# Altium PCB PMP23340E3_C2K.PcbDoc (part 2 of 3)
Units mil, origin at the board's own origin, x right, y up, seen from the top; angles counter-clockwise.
Board outline 2299.21 x 1157.48 mil, 14 copper layers (Top Layer, Layer 1, Layer 2, Layer 3, Layer 4, Layer 5, Layer 6, Layer 7, Layer 8, Layer 9, Layer 10, Layer 11, Layer 12, Bottom Layer), stack 130 mil thick; 241 components, 70 nets, 1009 pads, 327 vias.
Unrouted connection lines stored in the file: 7.
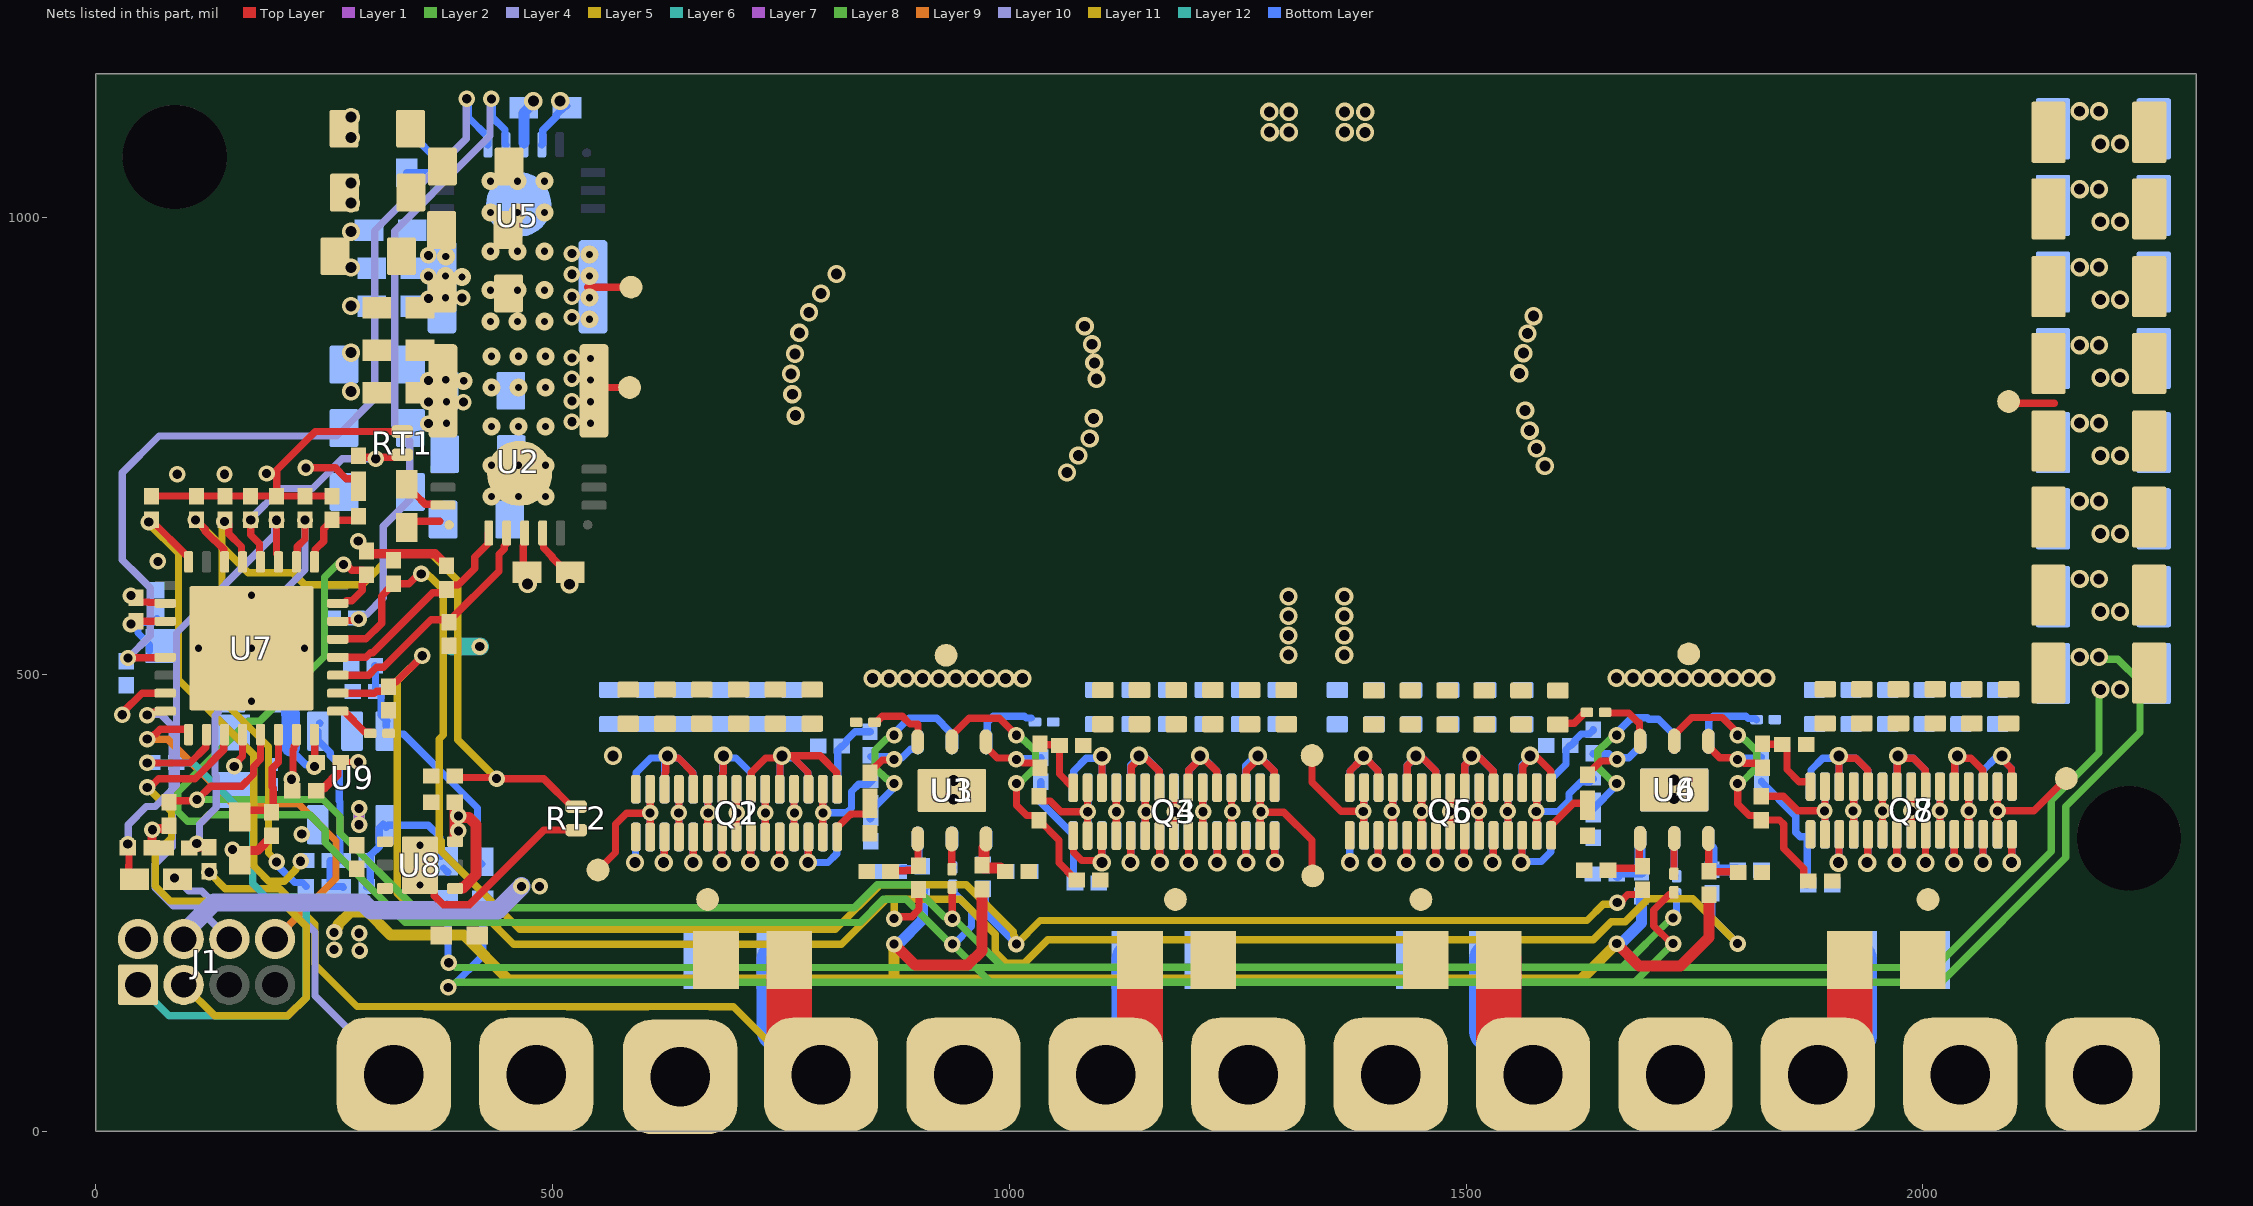
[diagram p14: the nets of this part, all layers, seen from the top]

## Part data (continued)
U7: library part CMP-0097759-1, "Real-Time Microcontrollers VQFN32 TMS320C28x 32bit 120MHz", Frequency_Fixed=120MHz, Manufacturer="Texas Instruments", Max Supply Voltage=3.63V, Min Supply Voltage=1.14V, Operating Temperature Range="-40°C to +125°C"
U8: library part CMP-0013427-7, "500mA LDO, DRV0006A (WSON-6)", Alternate Manufacturer="Texas Instruments"
U9: library part CMP-0032028-2, "CMOS Amplifier 1 Circuit Rail-to-Rail SOT-23-5", Digikey Part Number=296-TLV365DBVRCT-ND, Input Bias Current=0.000005uA, Input Offset Voltage=0.4mV, Manufacturer="Texas Instruments", Max Supply Voltage=5.5V, Min Supply Voltage=2.2V, Mouser Part Number=595-TLV365DBVR, Nominal Supply Current=4.6mA, Operating Temperature Range="-40°C to +125°C", Output Current Per Channel=85mA, Voltage Gain=120dB
ZZ1: library part CMP-0003616-3
ZZ2: library part CMP-0077236-1
ZZ3: library part CMP-0077237-1
ZZ4: library part CMP-0077238-1

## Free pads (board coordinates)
  round 114.17 hole 114.17 unplated: 2(86.41,1066.47) 2(2225.59,320.81)

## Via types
v1: diameter 20, hole 12, Top Layer to Bottom Layer, tented both sides, 153 vias
v2: diameter 18, hole 10, Top Layer to Bottom Layer, tented both sides, 121 vias
v3: diameter 19.68, hole 7.87, Top Layer to Bottom Layer, tented both sides, 51 vias
v4: diameter 19.68, hole 7.87, Top Layer to Bottom Layer, 2 vias

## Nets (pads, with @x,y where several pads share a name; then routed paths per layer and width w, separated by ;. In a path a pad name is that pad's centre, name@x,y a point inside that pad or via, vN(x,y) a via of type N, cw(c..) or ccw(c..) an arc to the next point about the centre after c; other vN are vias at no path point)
3_3V_A: C101.1 C133.1 R9.2 U7.11 | length 87.5
  Top Layer w8: C133.1@45.97,555.72 45.97,555.79 48.35,558.16 U7.11@75.96,558.15
  Bottom Layer w8: C101.1@58.86,525.62 58.86,532.64 46.14,545.35 46.14,552.38 50.83,557.06 63.17,557.06 R9.2@67.04,560.93
  other v2: 38.39,555.12
3_3V_D: C84.1 C106.1 C134.1 C135.1 R9.1 R10.2 R12.2 R31.2 R32.2 U7.15 U7.20 U7.23 U8.1 U9.5 | length 450.2
  Top Layer w8: v2@29.03,456.51 29.03,457.89 50.56,479.41 U7.15@75.96,479.41 ; v2@149.9,398.52 149.9,399.62 160.61,410.32 U7.20@160.61,434.14 ; v2(214.32,385.25) 215.98,386.91 215.98,417.59 216.9,418.51 216.9,421.64 218.74,423.48 218.74,433.21 U7.23@219.67,434.14 ; v2(230.03,726.08) 262.11,726.08 273.92,714.27 283.44,714.27 R31.2@288.04,709.67 ; R12.2@287.54,695.14 287.54,709.17 R31.2@287.71,709.34
  Top Layer w12: v2@288.7,354.31 v2@290.43,352.58
  Layer 1 w12: v2@287.23,333.89 288.33,334.99 v2(288.33,335.48) v2(288.33,353.31)
  Layer 2 w12: v2@288.33,334.82 v2(288.33,335.48) v2(288.33,353.31)
  Layer 4 w12: v2@288.12,335.32 v2(288.33,335.48) v2(288.33,353.31)
  Layer 5 w12: v2(288.33,353.31) 288.33,335.64 v2@288.47,335.5
  Layer 6 w12: v2(288.33,353.31) 288.33,337.95 v2@289.72,336.56
  Layer 7 w12: v2@288.12,336.56 288.33,336.77 v2(288.33,353.31)
  Layer 8 w12: v2@287.58,336.38 288.33,337.13 v2(288.33,353.31)
  Layer 9 w12: v2@287.41,336.03 288.33,336.95 v2(288.33,353.31)
  Layer 10 w12: v2@287.94,334.61 288.33,334.99 v2(288.33,335.48) v2(288.33,353.31)
  Layer 11 w12: v2@288.33,335.71 v2(288.33,353.31)
  Layer 12 w12: v2@287.05,334.61 v2@288.33,335.88 ; v2@287.23,334.43 v2(288.33,335.48) v2@288.33,335.88 ; v2(288.33,353.31) v2@288.33,335.88
  Bottom Layer w12: v2(288.33,353.31) v2(288.33,335.48) 288.33,335.19 v2@289.13,334.38
  other v2: 225.51,325.26 151.57,399.24 29.03,455.83 67.95,623.71
5V: C12.2 C48.2 C83.1 J1.2 L1.1 L2.1 L3.1 L4.1 U2.14 U5.14 U8.4 U8.6 | length 2270.2
  Top Layer w8: C12.2@467.81,616.28 467.81,641.21 468.61,642.01 U2.14@468.61,657.45 ; C12.2@471.58,615.54 472.77,614.34 v1(472.77,599.09)
  Top Layer w12: C83.1@392.99,360.1 393.21,359.88 393.21,344.89 v2@393.44,344.66 ; v2@393.06,325.22 393.06,316.99 393.16,316.9 U8.6@393.21,316.9 ; U8.6@393.28,316.9 U8.6@393.21,316.9 ; U8.4@396.14,265.81 398.65,265.81 399.22,266.39 401.78,266.39 416.14,280.74 416.14,335.7 408.33,343.52 394.58,343.52 v2@393.44,344.66 ; v2(873.92,204.75) 896.77,181.9 899.17,181.9 ; 899.17,181.75 954.97,181.75 ; 954.97,182.3 970.05,197.38 L2.1@970.05,265.17 ; v2(1664.88,205.38) 1689.35,180.91 1734.6,180.91 1765.81,212.12 L4.1@1765.81,258.78 1765.81,259.15 L4.1@1764.48,260.49 ; U8.6@393.21,316.9 393.12,316.99 393.12,328.11 392.95,328.28 393.19,328.52 393.19,344.42 v2@393.44,344.66
  Layer 1 w12: J1.2@46.09,206.08 J1.2@46.09,211.13
  Layer 11 w12: v2(260.93,217.57) 260.93,219.2 265.18,223.44 265.18,226.21 278.65,239.68 297.71,239.68 322.8,214.59 402.95,214.59 451.79,165.75 1619.05,165.75 ; 872.73,166.53 873.92,167.72 v2(873.92,204.75) ; 1619.05,165.67 1625.18,165.67 v2(1664.88,205.38)
  Bottom Layer w12: U5.14@468.5,1081.69 468.5,1114.8 479.51,1125.8 C48.2@479.51,1126.45 ; v2(873.92,204.75) 875.07,205.89 879.57,205.89 904.71,231.03 L1.1@904.71,263.99 904.71,265 L1.1@905.56,265.85 ; v2(1664.88,205.38) 1666.03,206.52 1670.53,206.52 1691.8,227.79 1691.8,257.17 L3.1@1690.96,258
  other v1: 479,1127.46
  other v2: 260.93,198.84 396.86,328.77 396.86,345.15
AGND: C83.2 C84.2 C85.2 C86.2 C87.2 C88.1 C89.1 C90.2 C91.2 C92.2 C93.2 C94.2 C95.2 C96.1 C100.2 C101.2 C103.1 C104.1 C106.2 C107.1 C108.1 C109.1 C133.2 C134.2 C135.2 C136.2 NT1.2 R11.1 R13.2 R23.1 R24.1 R26.1 RT1.2 RT2.2 U7.10 U7.33 U8.3 U8.7@354.9,291.31 U9.2 | length 969.4
  Top Layer w8: C133.2@44.85,584.75 44.85,582.73 48.35,579.23 57.32,579.23 57.79,578.76 75.04,578.76 U7.10@75.96,577.84 ; C88.1@61.15,695.09 61.27,695.21 C136.2@258.69,695.21 ; C104.1@197.97,695.22 197.97,723.72 240.18,765.92 RT1.2@335.5,765.92 335.64,765.92 RT1.2@335.99,766.27 ; C100.2@269.34,403.59 v2@287.41,403.59 ; U8.7@353.56,270.38 364.02,270.38 370.58,263.81 370.58,257.82 380.6,247.81 408.66,247.81 490.45,329.59 RT2.2@525.89,329.59
  Top Layer w10: R24.1@61.11,310.32 61.53,310.73 61.53,329.9 v2@61.21,330.21 ; R24.1@61.54,311 62.45,310.09 76.52,310.09 R23.1@76.57,310.04 ; v2@61.87,329.55 63.77,331.45 77.4,331.45 C90.2@80.1,334.15 ; v2(149.65,308.28) 157.78,300.15 R13.2@157.78,296.55 157.78,300.48 164.6,307.3 177.32,307.3 193.29,323.26 C85.2@193.38,323.26 ; U7.33@160.61,465.71 166.9,472 U7.33@171.22,472 ; C135.2@241.29,372.67 244.55,375.94 250.03,375.94 252.36,378.27 263.98,389.89 263.98,400.28 266.29,402.58 C100.2@266.29,403.16 ; v2@287.97,647.1 287.97,644.23 C91.2@296.29,635.91 ; C91.2@295.2,632.36 295.48,632.07 371.35,632.07 381.83,621.6 C92.2@381.83,619.47
  Layer 12 w20: 389.83,530.52 v2(420.27,530.52)
  other v2: 288.77,197.66 288.18,216.68 61.94,329.92 287.41,404.14 38.47,586.33 287.26,646.01 89.19,719.13 140.91,719.13 186.97,719.94
  other v3: 170.45,470.55 112.38,528.62 170.45,528.62 228.52,528.62 170.45,586.7
  other v4: 354.9,269.65 354.9,312.96
DCT2A: C91.1 R1.1 R44.1 U7.31 | length 2363.5
  Top Layer w8: U7.31@262.66,578.7 272.69,578.7 274.59,580.6 280.57,580.6 291.82,591.85 291.82,599.5 C91.1@296.08,603.77 ; v2@270.93,623.26 280.16,614.04 292.05,614.04 296.32,609.77 C91.1@296.32,609.11 ; v2@1726.73,205.42 1724.82,205.42 1705.55,224.7 1705.55,242.1 1722.12,258.67 1726.28,258.67 1727.45,259.84 R44.1@1727.45,261.64
  Layer 2 w8: v2@939.38,203.05 979.1,163.33 1684.5,163.33 v2(1726.55,205.38)
  Layer 8 w8: v2@267.87,624.02 250.37,606.51 250.37,519.58 179.5,448.71 166.79,448.71 89.81,371.72 89.81,349.89 100.3,339.4 116.88,339.4 123.74,346.26 234.2,346.26 251.33,329.14 251.33,315.93 338.79,228.47 836.7,228.47 862.01,253.77 886.98,253.77 936,204.75 v2(937.68,204.75)
  Bottom Layer w8: v2(937.68,204.75) 939.35,204.75 958.68,224.07 958.68,241.47 939.16,260.98 939.16,268.18 R1.1@938.52,268.82 ; v2@1723.45,205.67 v2@1728.51,205.67
  other v2: 271.14,620.34
DCT2B: C90.1 R38.1 R39.1 U7.21 | length 1957.5
  Top Layer w8: C90.1@78.47,360.06 79.99,361.58 109.36,361.58 v2(110.81,363.03) 111.08,363.03 125.79,377.74 159.77,377.74 172.57,390.54 172.57,399.06 180.3,406.78 180.3,433.58 U7.21@179.52,434.36 ; R38.1@937.66,267.45 937.47,267.25 937.47,232.98 v2(937.68,232.77)
  Layer 2 w8: v2(937.68,232.77) 939.35,232.77 992.8,179.33 1670.8,179.33 v2@1724.24,232.77
  Layer 8 w8: v2(110.81,363.03) 248.82,363.03 267.33,344.52 267.33,326.33 349.19,244.47 441.84,244.47 ; 442.98,244.47 830.08,244.47 855.38,269.77 893.61,269.77 928.69,234.68 935.76,234.68 v2(937.68,232.77)
  Bottom Layer w8: v2@1726.92,234.05 1726.92,236.48 1730.4,239.96 R39.1@1730.4,259.07
  other v2: 1726.55,233.4
GND: C1.1 C2.1 C3.1 C4.1 C5.1 C6.1 C7.1 C8.1 C9.1 C10.1 C11.2 C12.1 C14.1 C15.1 C16.1 C17.1 C18.1 C19.1 C20.1 C21.1 C22.1 C23.1 C24.1 C25.1 C26.1 C27.1 C28.1 C29.1 C30.1 C31.1 C32.1 C33.1 C34.1 C35.1 C36.1 C37.1 C38.2 C42.2 C48.1 C51.1 C52.1 C53.1 C54.1 C55.1 C56.1 C57.1 C58.1 C59.1 C60.1 C61.1 C62.1 C66.1 C67.1 C68.1 C69.1 C70.1 C71.1 C72.1 C73.1 C74.1 C75.1 C76.1 C77.1 C80.2 C97.1 C98.2 C99.1 C110.2 C111.1 C112.2 C113.1 C114.2 C115.2 C116.2 C117.2 C118.2 C119.2 C120.2 C121.2 C122.2 C123.2 C124.2 C125.2 C126.2 C127.2 C128.2 C129.1 C130.1 C131.1 C132.1 C137.1 C138.1 Gnd1.1 Gnd2.1 Gnd3.1 Gnd4.1 Gnd5.1 Gnd6.1 J1.4 NT1.1 Q1.2 Q1.5 Q1.6 Q1.9 Q1.10 Q1.13 Q1.14 Q1.17 Q1.18 Q1.21 Q1.22 Q1.25 Q1.26 Q1.29 Q1.30 Q2.2 Q2.5 Q2.6 Q2.9 Q2.10 Q2.13 Q2.14 Q2.17 Q2.18 Q2.21 Q2.22 Q2.25 Q2.26 Q2.29 Q2.30 Q3.2 Q3.5 Q3.6 Q3.9 Q3.10 Q3.13 Q3.14 Q3.17 Q3.18 Q3.21 Q3.22 Q3.25 Q3.26 Q3.29 Q3.30 Q4.2 Q4.5 Q4.6 Q4.9 Q4.10 Q4.13 Q4.14 Q4.17 Q4.18 Q4.21 Q4.22 Q4.25 Q4.26 Q4.29 Q4.30 Q5.2 Q5.5 Q5.6 Q5.9 Q5.10 Q5.13 Q5.14 Q5.17 Q5.18 Q5.21 Q5.22 Q5.25 Q5.26 Q5.29 Q5.30 Q6.2 Q6.5 Q6.6 Q6.9 Q6.10 Q6.13 Q6.14 Q6.17 Q6.18 Q6.21 Q6.22 Q6.25 Q6.26 Q6.29 Q6.30 Q7.2 Q7.5 Q7.6 Q7.9 Q7.10 Q7.13 Q7.14 Q7.17 Q7.18 Q7.21 Q7.22 Q7.25 Q7.26 Q7.29 Q7.30 Q8.2 Q8.5 Q8.6 Q8.9 Q8.10 Q8.13 Q8.14 Q8.17 Q8.18 Q8.21 Q8.22 Q8.25 Q8.26 Q8.29 Q8.30 R4.1 R8.1 R19.1 R22.1 R30.1 R34.1 R36.1 R45.1 TP12.1 TP13.1 TP14.1 TP15.1 U1.7@937.3,373.03 U2.6 U2.15 U3.7@937.01,373.03 U4.7@1727.87,373.66 U5.6 U5.15 U6.7@1727.87,373.66 | length 4876.3
  Top Layer w8: U2.15@489.22,654.82 490.14,653.9 490.14,638.49 499.79,628.84 499.79,627.62 C12.1@516.87,610.53 ; v1(518.55,598.71) 519.15,599.31 C12.1@519.15,612 ; v1(621.65,294.17) 622.2,294.73 622.2,321.65 Q1.25@622.83,322.28 ; Q1.26@623.07,369.66 623.07,392.64 623.76,393.34 623.76,408.53 v1(626.06,410.83) ; v1@626.02,411.34 628.84,408.53 637.81,408.53 652.72,393.62 ; 652.44,393.35 653.7,392.1 653.7,374.86 Q1.22@654.13,374.43 ; v1(653.96,294.17) 654.05,294.26 654.05,322.75 Q1.21@654.49,323.2 ; Q1.17@685.24,312.49 685.48,312.26 685.48,294.72 685.93,294.27 685.83,294.17 v1(685.33,294.17) ; Q1.18@685.93,379.23 686.06,379.36 686.06,391.66 686.89,392.49 v1(686.89,410.83) ; v1(716.53,294.17) 716.83,294.47 716.83,322.47 Q1.13@717.55,323.2 ; Q1.14@717.12,374.43 717.55,374.86 717.55,392.64 733.44,408.53 749.05,408.53 749.05,374.86 Q1.10@748.62,374.43 ; Q1.9@748.34,308.39 v1@748.34,294.21 ; v1@750.16,412.48 751.81,410.83 792.99,410.83 811.18,392.64 811.18,374.86 Q1.2@811.61,374.43 ; 763.79,408.53 779.68,392.64 779.68,374.86 Q1.6@780.11,374.43 ; v1(779.5,294.17) 779.81,294.48 779.81,316.24 Q1.5@779.68,316.36 ; Q3.2@1069.89,323.46 1070.32,323.03 1070.32,305.25 1079.25,296.32 1100.24,296.32 v1@1101.32,295.25 ; v1@1098.88,411.11 1101.38,408.61 Q3.5@1101.39,375.82 ; Q3.6@1101.39,323.46 1101.32,323.39 v1@1101.32,295.25 ; v1@1101.61,294.95 v1@1101.32,295.25 ; Q3.10@1132.88,323.46 1132.75,323.32 1132.75,295.71 v1@1134.64,293.81 ; Q3.9@1132.88,375.82 1133.32,376.26 1133.32,398.85 1141.7,407.23 v1@1141.7,410.83 ; v1@1142.38,411.11 1144.97,408.53 1149.45,408.53 1163.95,394.04 1163.95,376.26 Q3.13@1164.38,375.82 ; v1@1164.25,294.5 1164.65,294.9 1164.65,323.19 Q3.14@1164.38,323.46 ; v1@1194.54,291.31 1196.08,292.85 1196.08,323.25 Q3.18@1195.87,323.46 ; Q3.17@1195.87,375.82 1196.31,376.26 1196.31,395.1 v1@1209.58,408.37 ; v1@1209.12,410.2 1210.77,410.2 1226.94,394.04 1226.94,376.26 Q3.21@1227.37,375.82 ; v1@1226.2,292.22 1227.43,293.45 1227.43,323.4 Q3.22@1227.37,323.46 ; v1@1258.55,293.58 1259.1,294.14 1259.1,323.22 Q3.26@1258.87,323.46 ; Q3.25@1258.87,375.82 1259.3,376.26 1259.3,394.9 1273.35,408.95 v1@1273.35,410.43 ; v1@1272.44,411.11 1272.85,411.11 1289.93,394.04 1289.93,376.26 Q3.29@1290.36,375.82 ; Q3.30@1290.36,323.46 1290.53,323.29 1290.53,293.94 v1@1291.57,292.9 ; Q5.30@1372.56,376.14 1372.99,376.58 1372.99,394.36 1384.73,406.1 v1@1384.73,412.25 ; v1@1386.1,409.98 1388.35,409.98 1403.62,394.7 1403.62,376.58 Q5.26@1404.05,376.14 ; v1@1402.04,294.72 1403.62,296.3 1403.62,323.35 Q5.25@1404.05,323.78 ; v1@1434.61,295.18 1435.12,295.68 1435.12,323.35 Q5.21@1435.55,323.78 ; Q5.22@1435.55,376.14 1435.55,400.21 v1@1445.32,409.98 ; v1@1445.32,408.57 1452.41,408.57 1466.61,394.36 1466.61,376.58 Q5.18@1467.05,376.14 ; v1@1466.96,294.72 1466.61,295.07 1466.61,323.35 Q5.17@1467.05,323.78 ; v1@1497.02,293.58 1498.11,294.67 1498.11,323.35 Q5.13@1498.54,323.78 ; Q5.14@1498.54,376.14 1498.54,400.63 1503.36,405.45 1503.36,411.38 v1@1503.17,411.57 ; v1@1504.08,411.8 1507.32,408.57 1515.4,408.57 1529.61,394.36 1529.61,376.58 Q5.10@1530.04,376.14 ; Q5.9@1530.04,323.78 1529.61,323.35 1529.61,293.57 v1@1530.28,292.9 ; v1@1560.57,291.99 1561.1,292.52 1561.1,323.35 Q5.5@1561.54,323.78 ; Q5.6@1561.54,376.14 1561.97,376.58 1561.97,399.62 1568.77,406.43 v1@1568.77,409.52 ; v1@1570.36,409.52 1571.32,408.57 1578.39,408.57 1592.6,394.36 1592.6,376.58 Q5.2@1593.03,376.14 ; C31.1@1600.51,444.67 1602.33,446.49 1618.31,446.49 1629.21,457.39 1631.01,457.39 R45.1@1632.18,458.56 ; v1@1908.15,292.9 1908.11,292.94 1908.11,324.49 Q7.6@1908.51,324.89 ; v1@1908.27,406.67 1908.27,377.49 Q7.5@1908.51,377.25 ; v1@1909.06,410.66 1911.41,408.31 1926.73,408.31 1939.57,395.47 1939.57,377.68 Q7.9@1940.01,377.25 ; v1@1938.44,292.45 1939.57,293.57 1939.57,324.46 Q7.10@1940.01,324.89 ; v1@1971.45,294.75 1971.45,324.83 Q7.14@1971.5,324.89 ; Q7.13@1971.5,377.25 1971.93,377.68 v1@1971.93,410.61 ; v1@1972.15,411.11 1974.96,408.31 1989.72,408.31 2002.57,395.47 2002.57,377.68 Q7.17@2003,377.25 ; Q7.18@2003,324.89 2002.88,324.77 2002.88,294.52 v1@2003.13,294.27 ; v1@2034.11,293.81 2034.23,293.93 2034.23,324.62 Q7.22@2034.49,324.89 ; Q7.21@2034.49,377.25 2034.93,377.68 2034.93,404.61 2037.3,406.98 v1@2037.3,409.75 ; v1@2034.79,412.25 v1@2037.3,409.75 ; v1@2037.3,412.03 v1@2037.3,409.75 ; Q7.26@2065.99,324.89 2065.9,324.79 2065.9,293.91 v1@2066.22,293.58 ; Q7.25@2065.99,377.25 2065.56,377.68 2065.56,395.47 2052.71,408.31 2038.73,408.31 v1@2037.3,409.75 ; v1@2088.32,409.29 2088.32,405.74 2097.05,397.01 2097.05,377.68 Q7.29@2097.49,377.25 ; Q7.30@2097.49,324.89 2097.33,324.73 2097.33,295.96 v1@2098.34,294.95 ; v1@748.34,294.21 v1(748.37,294.17)
  Layer 4 w20: J1.4@96.2,210.27 96.2,216.79 106.15,226.74 106.15,226.86 129.61,250.32 292.72,250.32 301.23,241.81 439.78,241.81 v2@465.99,268.02
  Bottom Layer w8: U5.15@488.19,1079.72 489.11,1080.65 489.11,1095.58 504,1110.46 504,1112.27 513.84,1122.1 C48.1@515.64,1122.1 ; v1@587.54,294.27 590.71,297.44 590.71,321.64 Q2.30@591.14,322.06 ; Q2.29@591.14,374.43 591.57,374.86 591.57,392.64 607.46,408.53 v1@622.84,408.53 ; v1(621.65,294.17) 622.2,294.73 622.2,322.84 Q2.26@622.54,323.18 ; Q2.25@622.63,374.43 622.63,404.15 623.76,405.28 623.76,409.05 v1@622.84,409.98 ; v1@623.75,411.8 627.02,408.53 637.81,408.53 653.7,392.64 653.7,374.86 Q2.21@654.13,374.43 ; v1@654.05,297 654.05,321.98 Q2.22@654.13,322.06 ; v1@683.66,294.27 685.48,296.09 685.48,321.92 Q2.18@685.63,322.06 ; v1@683.88,412.71 688.06,408.53 700.8,408.53 716.69,392.64 716.69,374.86 Q2.13@717.12,374.43 ; Q2.17@685.63,374.43 686.06,374.86 v1@686.06,409.87 ; Q2.18@685.72,321.97 Q2.18@685.76,322.01 ; v1(716.53,294.17) 714.93,294.17 714.86,294.25 716.83,296.22 716.83,318.86 Q2.14@716.69,319 ; v1@748.11,294.27 748.5,294.65 748.5,321.94 Q2.10@748.62,322.06 ; Q2.9@748.62,374.43 749.05,374.86 v1@749.05,410.83 ; v1@751.53,410.89 753.89,408.53 763.79,408.53 779.68,392.64 779.68,374.86 Q2.5@780.11,374.43 ; v1@779.81,292.93 779.81,321.76 Q2.6@780.11,322.06 ; v1@780.78,294.17 801.5,294.17 811.18,303.85 811.18,321.63 Q2.2@811.61,322.06 ; Q4.2@1069.98,376.14 1070.42,376.57 1070.42,394.35 1084.2,408.14 1099.09,408.14 v1@1100.02,409.06 ; v1@1100.93,296.32 1101.36,296.75 1101.36,323.66 Q4.5@1101.48,323.78 ; v1@1101.43,408.88 1101.43,376.19 Q4.6@1101.48,376.14 ; v1@1130.77,296.09 1132.79,298.11 1132.79,323.59 Q4.9@1132.98,323.78 ; Q4.10@1132.98,376.14 1132.98,400.6 1139.88,407.5 v1@1139.88,411.8 ; v1@1142.59,411.37 1145.43,408.53 1149.86,408.53 1164.04,394.35 1164.04,376.57 Q4.14@1164.47,376.14 ; Q4.13@1164.47,323.78 1164.7,323.55 1164.7,295.41 v1@1165.85,294.27 ; v1@1195.23,294.95 1196.13,295.85 1196.13,323.62 Q4.17@1195.97,323.78 ; Q4.18@1195.97,376.14 1196.4,376.57 1196.4,395.19 1206.62,405.41 v1@1206.62,410.43 ; v1@1212.09,409.29 1227.03,394.35 1227.03,376.57 Q4.22@1227.46,376.14 ; Q4.21@1227.46,323.78 1227.48,295.72 v1@1228.48,294.72 ; Q4.25@1258.96,323.78 1259.15,323.59 1259.15,293.21 v1@1259.23,293.13 ; Q4.26@1258.96,376.14 1258.96,399.91 v1@1269.94,410.89 ; v1@1273.81,410.57 1290.02,394.35 1290.02,376.57 Q4.30@1290.46,376.14 ; Q4.29@1290.46,323.78 1290.58,323.65 1290.58,295.04 v1@1290.66,294.95 ; v1@1372.43,295.18 1372.8,295.54 1372.8,323.55 Q6.30@1372.56,323.78 ; Q6.29@1372.56,376.14 1372.99,376.58 1372.99,394.36 v1@1385.65,407.01 ; v1@1388.38,409.52 1388.81,409.52 1403.62,394.7 1403.62,376.58 Q6.25@1404.05,376.14 ; v1@1401.36,293.59 1403.62,295.85 1403.62,323.35 Q6.26@1404.05,323.78 ; Q6.22@1435.55,323.78 1435.12,323.35 1435.12,296.73 v1@1436.21,295.63 ; Q6.21@1435.55,376.14 1435.55,400.43 v1@1444.64,409.52 ; v1@1447.83,412.25 1447.83,411.24 1450.5,408.57 1452.41,408.57 1466.61,394.36 1466.61,376.58 Q6.17@1467.05,376.14 ; v1@1466.28,294.5 1466.61,294.83 1466.61,323.35 Q6.18@1467.05,323.78 ; v1@1496.11,292.45 1498.11,294.44 1498.11,323.35 Q6.14@1498.54,323.78 ; Q6.13@1498.54,376.14 1498.54,400.63 v1@1504.09,406.18 ; v1@1507.05,411.11 1509.6,408.57 1515.4,408.57 1529.61,394.36 1529.61,376.58 Q6.9@1530.04,376.14 ; v1@1527.32,294.04 1529.61,296.33 1529.61,323.35 Q6.10@1530.04,323.78 ; v1@1559.89,294.04 v1@1561.1,295.25 ; Q6.6@1561.54,323.78 1561.1,323.35 1561.1,295.3 1582.33,295.3 1592.6,305.57 1592.6,323.35 Q6.2@1593.03,323.78 ; Q6.5@1561.54,376.14 1561.54,400.63 1567.41,406.5 v1@1567.41,412.25 ; Q8.2@1877.01,377.25 1877.45,377.68 1877.45,395.47 1890.29,408.31 1905.58,408.31 v1@1907.01,409.75 ; v1@1907.92,291.53 1908.11,291.72 1908.11,324.49 Q8.5@1908.51,324.89 ; v1@1908.27,408.94 1908.27,377.49 Q8.6@1908.51,377.25 ; v1@1908.9,408.31 1926.73,408.31 1939.57,395.47 1939.57,377.68 Q8.10@1940.01,377.25 ; v1@1938.9,292.9 1939.57,293.57 1939.57,324.46 Q8.9@1940.01,324.89 ; v1@1969.42,294.5 1971.45,296.52 1971.45,324.83 Q8.13@1971.5,324.89 ; v1@1971.47,410.66 1971.93,410.2 1971.93,377.68 Q8.14@1971.5,377.25 ; v1@1974.2,410.66 1976.55,408.31 1989.72,408.31 2002.57,395.47 2002.57,377.68 Q8.18@2003,377.25 ; v1@2002.22,293.81 2002.88,294.47 2002.88,324.77 Q8.17@2003,324.89 ; Q8.21@2034.49,324.89 2034.23,324.62 2034.23,294.6 v1@2034.79,294.04 ; Q8.22@2034.49,377.25 2034.93,377.68 2034.93,404.61 2036.84,406.53 v1@2036.84,410.89 ; Q8.25@2065.99,324.89 2065.9,324.79 2065.9,296.87 v1@2067.13,295.63 ; Q8.26@2065.99,377.25 2066.42,377.68 2066.42,395.47 2079.27,408.31 2082.1,408.31 v1@2084.67,410.89 ; v1@2087.18,406.88 2097.05,397.01 2097.05,377.68 Q8.30@2097.49,377.25 ; v1@2096.06,295.18 2097.33,296.44 2097.33,324.73 Q8.29@2097.49,324.89
  other v1: 590.28,294.17 1101.25,294.17 1132.61,294.17 1164.93,294.17 1196.29,294.17 1227.5,294.17 1259.34,294.17 1290.7,294.17 1373.03,294.29 1402.24,294.21 1434.55,294.21 1465.92,294.21 1497.12,294.21 1528.96,294.21 1560.33,294.21 1907.71,293.96 1939.07,293.96 1971.39,293.96 2002.75,293.96 2033.96,293.96 2065.8,293.96 2097.17,293.96 938.68,363.34 1727.55,363.97 938.68,384.03 1727.55,384.66 566.06,410.83 751.06,410.83 1101.38,410.43 1142.05,410.83 1208.79,410.83 1271.98,410.83 1387.46,410.86 1444.96,410.86 1505.79,410.86 1569.96,410.86 1908.03,410.61 1973,410.61 2037.68,410.61 2086.7,410.61 279.32,809.88 279.32,852.18 279.32,903.25 279.32,945.55 279.32,984.65 279.32,1015.9 279.32,1038.12 279.32,1087.73 279.32,1109.95 508.28,1127.73
  other v2: 465.84,268.03 485.86,268.03
  other v3: 433.11,694.66 462.64,694.66 492.17,694.66 433.11,728.91 462.64,728.91 492.17,728.91 433.11,771.43 462.64,771.43 492.17,771.43 433.11,813.95 462.64,813.95 492.17,813.95 433.11,848.21 462.64,848.21 492.17,848.21 432.09,886.34 461.61,886.34 491.14,886.34 432.09,920.59 461.61,920.59 491.14,920.59 432.09,963.11 461.61,963.11 491.14,963.11 432.09,1005.63 461.61,1005.63 491.14,1005.63 432.09,1039.88 461.61,1039.88 491.14,1039.88
IOCP: C88.2 R18.2 U7.8 | length 556.6
  Top Layer w8: v2(58,666.77) 62.63,666.77 98.47,630.92 100.63,630.92 101.67,629.89 U7.8@101.67,624.28
  Layer 5 w8: v2@58,665.03 90.54,632.49 90.54,494.23 172.75,412.01 172.75,290.73 176.98,286.5 176.98,286.06 189.28,273.76 206.68,273.76 218.98,286.06 218.98,287.46 224.26,292.73 v2(224.26,295.44)
IOSNS: C89.2 R27.2 U7.5 | length 500.5
  Top Layer w8: v2(140.8,667.38) 142.45,667.38 145.65,664.18 145.65,653.88 159.54,639.99 U7.5@159.54,622.59
  Layer 5 w8: v2@138.1,671.67 138.1,472.01 188.97,421.15 188.97,304.44 197.98,295.43 v2(197.98,294.76)
  Bottom Layer w8: v2(197.98,294.76) 199.9,292.84 199.9,290.1 217.86,272.14 226.2,272.14 R27.2@230.47,267.87
JTAG_TCK: J1.6 U7.16 | length 347.2
  Top Layer w8: v2(56.36,455.51) 59.07,455.51 62.36,458.81 75.84,458.81 U7.16@76.89,459.85 ; J1.6@141.72,210.49 J1.6@146.42,210.49
  Layer 10 w8: v2@58.17,456.41 70.95,456.41 83.8,443.56 83.8,311.32 65.23,292.75 65.23,266.19 84.48,246.94 109.53,246.94 J1.6@146.2,210.27
JTAG_TDI: J1.3 U7.19 | length 661.7
  Top Layer w8: v2(56.36,376.35) 59.07,376.35 68.64,385.93 108.53,385.93 140,417.41 140,433.21 U7.19@140.93,434.14
  Layer 5 w8: v2(56.36,376.35) 82.94,349.77 82.94,321.22 65.23,303.51 65.23,268.32 81.57,251.98 202.64,251.98 230.25,224.37 230.25,146.17 210.3,126.22 130.25,126.22 96.95,159.52 J1.3@96.18,159.52
JTAG_TDO: J1.8 U7.17 | length 440.1
  Top Layer w8: v2(56.36,429.22) 59.07,429.22 64.36,434.51 65.06,434.51 70.64,440.09 100.63,440.09 102.08,438.65 U7.17@102.08,438 ; J1.8@195.81,211.35 J1.8@197.28,211.35
  Layer 9 w8: v2(56.36,429.22) 78.77,429.19 149.71,358.26 222.21,358.26 262.91,317.56 262.91,276.98 J1.8@196.59,210.66
JTAG_TMS: J1.1 R10.1 U7.18 | length 677.7
  Top Layer w8: v2(56.36,403.11) 103.08,403.11 120.32,420.35 120.32,439 U7.18@121.88,440.56
  Layer 6 w8: J1.1@45.7,160.92 45.7,160.77 J1.1@46.2,160.27 80.25,126.22 210.3,126.22 230.25,146.17 230.25,246.4 220.21,256.44 186.37,256.44 171.71,271.1 171.71,338.36 106.96,403.11 v2(56.36,403.11)
NetC11_1: C11.1 L1.2 U1.3 | length 55.6
  Bottom Layer w8: C11.1@879.13,284.45 881.9,287.21 L1.2@903.15,287.21 ; U1.3@899.89,319.88 901,318.78 901,294.91 L1.2@904.54,291.37
NetC13_1: C13.1 U2.10 | length 45
  Top Layer w8: C13.1@343.65,703.22 343.65,701.01 348.29,696.37 350.5,696.37 360.61,686.25 379.04,686.25 U2.10@379.96,685.33
NetC13_2: C13.2 U2.11 | length 40.1
  Top Layer w8: C13.2@340.29,659.18 340.29,659.51 348.58,667.8 376.67,667.8
NetC38_1: C38.1 L2.2 U3.3 | length 60.4
  Top Layer w12: U3.3@974.59,320.1 974.59,312.69 972.32,310.42 972.32,293.28 L2.2@970.05,291.01 970.05,290.35 972.32,288.08 990.56,288.08 995,283.64 C38.1@995,282.56
NetC42_1: C42.1 L3.2 U4.3 | length 65.9
  Bottom Layer w12: C42.1@1665.81,279.95 1665.81,281.4 1667.87,283.46 L3.2@1691.8,283.46 1690.47,284.79 U4.3@1690.47,320.51
NetC50_1: C50.1 U5.10 | length 45.1
  Bottom Layer w8: C50.1@340.55,1049.21 U5.10@378.94,1049.21 384.36,1049.21 U5.10@385.29,1050.14
NetC50_2: C50.2 U5.11 | length 61
  Bottom Layer w8: C50.2@340.55,1096.46 340.55,1092.52 348.36,1084.71 352.3,1084.71 368.01,1069 U5.11@387.86,1069
NetC80_1: C80.1 L4.2 U6.3 | length 68.2
  Top Layer w8: U6.3@1763.7,318.15 1765.54,316.3 L4.2@1765.54,285.19 ; L4.2@1764.07,285.19 1765.23,284.02 1797.06,284.02 C80.1@1797.8,283.29
NetC96_2: C96.2 C100.1 U7.24 | length 127.3
  Top Layer w8: U7.24@238.73,436.46 239.55,435.64 C100.1@239.55,404.11
  Bottom Layer w8: 213.3,420.02 213.3,417.44 229.73,401.01 237.32,401.01 v2(239.23,399.09)
  Bottom Layer w20: C96.2@207.07,475.91 212.82,470.16 212.82,456.96 213.3,456.48 213.3,420.02
NetC97_2: C97.2 Q1.1 R3.1 | length 65.4
  Top Layer w8: Q1.1@811.61,322.06 811.61,332.38 826.11,346.88 827.37,346.88 ; 827.38,347.16 C97.2@843.19,347.16 ; C97.2@846.47,349.2 847.46,350.18 C97.2@847.46,352.09 R3.1@847.46,366.31
NetC98_1: C98.1 Q2.1 R5.2 | length 78
  Bottom Layer w8: Q2.1@812.07,384.21 812.07,385.12 812.31,385.36 812.31,417.24 816.58,421.51 C98.1@816.71,421.51 ; C98.1@816.92,420.93 821.77,425.78 821.77,427.92 831.13,437.29 R5.2@847.6,437.29
NetC99_2: C99.2 Q3.1 R7.1 | length 70.4
  Top Layer w8: R7.1@1033.45,424 1034.33,423.12 C99.2@1052.31,423.12 ; C99.2@1054.92,422.24 1054.92,390.94 Q3.1@1068.95,376.91
NetC105_1: C105.1 R16.1 R18.1 R27.1 U9.1 | length 208.5
  Bottom Layer w8: U9.1@243.11,437.99 243.11,428.15 256.7,414.56 256.7,411.33 266.41,401.62 266.41,361.59 267.33,360.67 267.33,298.81 C105.1@269.23,296.91 ; U9.1@245.29,446.41 U9.1@245.36,446.48 ; R27.1@255.99,267.88 256.07,267.8 269.92,267.8 R16.1@270.86,266.85 ; R27.1@256.31,268.2 R18.1@256.31,296.37 C105.1@269.23,296.37 ; R16.1@270.39,267.8 R16.1@270.47,267.72
NetC105_2: C105.2 R16.2 R17.2 U9.4 | length 168.4
  Bottom Layer w8: R16.2@296.46,267.72 300.31,271.57 C105.2@300.31,302.32 ; C105.2@301.12,302.34 310.31,311.53 310.31,331.52 U9.4@314.69,335.9 ; U9.4@317.91,332.68 320.04,334.8 363.94,334.8 376.74,322.01 376.74,319.19 377.53,318.4 R17.2@377.53,300.9 ; R17.2@380.53,288.17 R17.2@385.16,283.54
NetC107_2: C107.2 R25.2 R26.2 U9.3 | length 268.8
  Bottom Layer w8: R26.2@305.4,509.5 306.27,508.63 306.27,483.13 C107.2@307.8,481.59 ; C107.2@307.13,481.45 307.92,481.45 312.18,477.18 312.18,455.35 U9.3@318.73,448.8 ; U9.3@318.1,437.15 320.57,434.68 337.04,434.68 417.86,353.85 417.86,297.31 R25.2@422.72,292.45 ; U9.3@318.12,443.31 U9.3@318.12,447.6
NetC110_1: C110.1 Q4.1 R37.2 | length 124.3
  Bottom Layer w8: R37.2@1034.45,382.68 1034.45,359.95 Q4.1@1068.84,325.55 ; Q4.1@1069.98,323.78 1070.19,323.57 1070.19,274.88 C110.1@1072.96,272.11
NetC111_2: C111.2 Q5.1 R40.1 | length 77.4
  Top Layer w8: Q5.1@1593.03,323.78 1593.37,324.12 Q5.1@1593.37,336.63 ; Q5.1@1594.37,335.64 1617.65,358.92 1628.61,358.92 1632.5,362.82 R40.1@1632.5,363.98 ; C111.2@1631.98,350.1 C111.2@1632.18,350.3 ; C111.2@1632.87,349.61 R40.1@1632.87,363.19
NetC112_1: C112.1 Q6.1 R41.2 | length 76.4
  Bottom Layer w8: Q6.1@1593.49,385.92 1609.34,401.77 1609.34,417.77 1613.61,422.04 C112.1@1613.87,422.04 ; C112.1@1615.57,422.96 1618.92,426.31 1618.92,427.65 1625.96,434.68 1634.93,434.68 1639.2,438.95 R41.2@1639.2,439.61
NetC113_2: C113.2 Q7.1 R42.1 | length 87.3
  Top Layer w8: R42.1@1824.36,424 1824.75,423.62 C113.2@1845.78,423.62 ; C113.2@1846.26,423.23 1846.92,423.23 1851.19,418.96 1851.19,395.87 1864.39,382.68 1875.7,382.68 1877.01,381.36 Q7.1@1877.01,377.25
NetC114_1: C114.1 Q8.1 R43.2 | length 138.5
  Bottom Layer w8: R43.2@1823.34,383.31 1823.34,382.52 1860.95,344.91 1860.95,327.07 1865.64,322.38 1872.14,322.38 Q8.1@1872.54,321.98 ; C114.1@1872.94,269.22 1873.48,269.75 Q8.1@1873.48,321.98
NetC129_2: C129.2 R14.2 U1.1 | length 56.1
  Bottom Layer w8: R14.2@971.46,291.54 973.59,293.67 973.59,320.62 U1.1@976.1,323.12 ; R14.2@975.72,287.99 993.31,287.99 C129.2@996.85,284.45
NetC130_2: C130.2 R15.2 U3.1 | length 61.4
  Top Layer w8: C130.2@871.2,285.07 886.81,285.07 887.35,285.62 896.32,285.62 900.1,289.4 900.1,319.39 U3.1@899.61,319.88
NetC131_2: C131.2 R28.2 U4.1 | length 65.8
  Bottom Layer w12: U4.1@1765.27,320.51 1765.27,313.14 1769.16,309.26 R28.2@1769.16,286.33 ; R28.2@1769,286.21 1769.29,285.92 1796.32,285.92 C131.2@1798.12,284.12
NetC132_2: C132.2 R29.2 U6.1 | length 71.9
  Top Layer w8: C132.2@1655.32,285.6 1657.58,287.86 R29.2@1691.93,287.86 ; U6.1@1689.63,322.96 1689.63,293.7 R29.2@1693.21,290.11
NetR1_2: R1.2 U1.2 | length 32.4
  Bottom Layer w6: U1.2@937.3,319.88 937.64,319.53 937.64,289.43 R1.2@938.93,288.14
NetR2_1: R2.1 R4.2 U1.5 | length 211.1
  Layer 2 w8: v2@873.92,434.33 871.22,434.33 866.14,429.26 865.22,429.26 852.92,416.96 852.92,397.99 865.18,385.74 866.26,385.74 870.69,381.31 v2@874.63,381.31
  Bottom Layer w8: R4.2@847.69,341.64 848.29,342.24 R4.2@848.29,343.35 R2.1@848.29,358.7 ; R2.1@852.45,354.55 872.01,374.11 872.01,379.08 v2@873.92,380.99 ; v2@874.81,436.69 890.08,451.96 920.39,451.96 934.41,437.95 934.41,437.52 937.3,434.63 U1.5@937.3,428.17
  other v2: 873.92,380.79 873.92,433.35
NetR6_1: R6.1 R8.2 U3.5 | length 294.3
  Top Layer w8: U3.5@938.04,432.58 938.04,434.17 955.83,451.96 989.14,451.96 v2(1007.75,433.35) ; v2@1005.89,378.21 1007.75,376.35 1007.75,356.91 1019.18,345.49 1028.15,345.49 1032.41,341.22 R6.1@1032.41,340.56 1054.35,318.63 1054.35,293.69 1070.6,277.43 R8.2@1072.05,277.43
  Layer 2 w8: v2(1007.75,433.35) 1010.46,433.35 1015.78,428.03 1016.45,428.03 1028.75,415.73 1028.75,398.34 1013.12,382.7 1012.37,382.7 1009.52,379.84 v2@1009.52,378.81
  other v2: 1007.75,380.79
NetR11_2: R11.2 U7.25 | length 45.7
  Top Layer w8: U7.25@264.94,459.73 271.83,459.73 294.55,437.01 R11.2@301.2,437.01
NetR19_2: R19.2 U3.6 | length 73.1
  Top Layer w8: R19.2@852.42,447.69 854.21,447.69 860.87,454.35 882.62,454.35 891.18,445.79 899.97,445.79 U3.6@899.97,426.62
NetR22_2: R22.2 U1.6 | length 74.1
  Bottom Layer w8: U1.6@974.7,426.18 975.8,427.29 975.8,447.63 982.52,454.35 1016.45,454.35 1018.48,452.32 R22.2@1024.35,452.32
NetR30_2: R30.2 U4.6 | length 78.2
  Bottom Layer w8: U4.6@1765.27,426.81 1765.6,427.14 1765.6,451.4 ; 1767.32,451.4 1770.27,454.35 1805.97,454.35 1808.63,451.69 1816.78,451.69 R30.2@1817.95,450.52
NetR33_1: R33.1 R34.2 U4.5 | length 199.1
  Layer 2 w8: v2(1664.88,433.35) 1662.17,433.35 1656.86,428.03 1656.57,428.03 1644.27,415.73 1644.27,398.34 1659.91,382.7 1664.36,382.7 v2@1667.42,379.63
  Bottom Layer w8: R33.1@1638.08,353.59 1639.63,353.59 v2@1662.97,376.92 ; v2@1665.39,432.08 1665.39,436.57 1679.77,450.94 1681,450.94 1682.65,452.59 1698.29,452.59 1699.94,450.94 1710.63,450.94 1727.87,433.7 U4.5@1727.87,426.81
  other v2: 1664.88,380.79
NetR35_1: R35.1 R36.2 U6.5 | length 322.1
  Top Layer w8: U6.5@1727.03,432.86 1746.96,452.79 1780.54,452.79 1797.52,435.81 v2@1797.52,433.1 ; v2(1797.27,380.79) 1797.27,358.09 1809.87,345.49 1819.23,345.49 R35.1@1823.28,341.44 ; R35.1@1823.11,339.77 R35.1@1823.11,340.56 1843.11,340.56 1847.8,335.87 1847.8,309.38 1869.61,287.57 1869.61,278.12 R36.2@1874.93,272.8
  Layer 2 w8: v2@1794.97,380.82 1796.84,382.7 1802.64,382.7 1818.27,398.34 1818.27,415.73 1805.97,428.03 1805.29,428.03 1799.98,433.35 v2(1797.27,433.35)
NetR38_2: R38.2 U3.2 | length 32.7
  Top Layer w8: R38.2@937.26,286.84 937.14,286.97 937.14,318 U3.2@938.22,319.08
NetR39_2: R39.2 U4.2 | length 41.8
  Bottom Layer w8: U4.2@1727.87,320.51 1727.87,280.48 R39.2@1729.15,279.21
NetR44_2: R44.2 U6.2 | length 44.3
  Top Layer w8: R44.2@1727.45,281.66 1727.66,281.87 1727.66,324.7 U6.2@1728.51,325.56
NetR45_2: R45.2 U6.6 | length 60.3
  Top Layer w8: R45.2@1653.29,457.74 1678.07,457.74 1688.39,447.42 ; 1689.74,447.42 1689.74,427.54 U6.6@1690.47,426.81
PWM1A: C92.1 U2.12 U7.28 | length 237.6
  Top Layer w8: U7.28@264.94,518.78 295.7,518.78 300.63,523.71 303.15,523.71 368.9,589.46 379.44,589.46 385.65,595.67 385.65,597.87 396.94,597.87 414.92,615.85 414.92,628.63 429.24,642.95 429.24,654.52 U2.12@430.33,655.61
PWM1B: C93.1 U2.13 U7.27 | length 272.9
  Top Layer w8: U7.27@264.94,499.1 298.64,499.1 307.25,507.71 314.94,507.71 366.96,559.72 384.06,559.72 C93.1@386.52,557.26 ; C93.1@386.52,558.05 441.41,612.93 441.41,631.55 447.08,637.22 447.08,640.35 448.93,642.2 448.93,656.07 U2.13@449.89,657.03
PWM2A: C95.1 R14.1 R29.1 U7.29 | length 1963.3
  Top Layer w8: U7.29@264.94,538.47 265.51,539.04 295.85,539.04 312.94,556.13 312.94,585.88 321.22,594.16 321.51,594.16 325.78,598.43 C95.1@325.78,599.21 342.77,599.21 355.72,612.16 v2@357.32,612.16 ; v2(1665.41,250.23) 1668.11,250.23 1676.95,259.07 1688.94,259.07 1694.15,264.28 R29.1@1694.15,265.24
  Layer 11 w8: v2@358.04,614.14 365.44,606.74 366.01,606.74 380.33,592.43 380.33,433.74 375.86,429.27 375.86,322.89 375.86,320.07 378.32,317.61 378.32,306.4 463.97,220.75 809.57,220.75 858.6,269.77 953,269.77 1004.62,218.16 1004.62,214.43 1005.84,213.21 1005.84,209.18 v2@1004.62,207.96 ; v2(1007.75,204.75) 1033.66,230.66 1632.44,230.66 1650.1,248.32 1663.04,248.32 v2@1664.95,250.23
  Bottom Layer w8: R14.1@970.56,265.42 973.49,262.49 973.49,249.29 974.68,248.1 974.68,237.82 v2(1007.75,204.75)
  other v2: 356.27,610.07
PWM2B: C94.1 R15.1 R28.1 U7.26 | length 2129.6
  Top Layer w8: U7.26@264.94,479.41 304.94,479.41 307.25,481.72 316.22,481.72 320.49,485.99 320.49,487.44 324.76,491.71 328.97,491.71 v2@357.32,520.06 ; v2(873.92,232.77) 875.84,234.68 893.07,234.68 901.2,242.81 R15.1@901.2,266.41 ; R15.1@898.64,261.83 R15.1@900.76,259.71
  Layer 11 w8: v2@358.25,521.32 330,493.07 330,260.58 354.32,236.25 425.84,236.25 457.34,204.75 816.2,204.75 865.22,253.77 874.43,253.77 ; v2(873.92,232.77) 873.92,253.27 874.43,253.77 ; v2@1796.92,205.18 1796.92,205.73 1748.25,254.4 1699.27,254.4 1674.1,229.23 1659.04,229.23 1639.21,209.41 1042.11,209.41 1016.45,183.75 996.78,183.75 984.46,196.07 984.46,215.69 946.38,253.77 874.43,253.77
  Bottom Layer w8: R28.1@1769.02,260.67 1769.02,233.62 v2(1797.27,205.38)
  other v2: 357.38,520.45
PWM3A: C87.1 U5.12 U7.13 | length 1001.4
  Top Layer w8: v2@35.26,518.53 35.42,518.37 75.56,518.37 U7.13@75.96,518.78
  Layer 4 w8: v2(35.26,517.97) 59.47,542.17 59.47,595.03 47.17,607.33 46.96,607.33 29,625.3 29,720.9 69.17,761.07 264.05,761.07 305.3,802.32 305.3,985.86 405.63,1086.19 v2@405.63,1128.11
  Bottom Layer w8: v2@405.58,1126.52 407.06,1126.52 408.01,1125.57 408.01,1109.71 429.13,1088.58 U5.12@429.13,1079.72
  other v2: 406.09,1130.19
PWM3B: C86.1 U5.13 U7.30 | length 716.5
  Top Layer w8: U7.30@264.94,558.15 265.86,559.07 286.19,559.07 v2(287.78,560.66)
  Layer 4 w8: v2(287.78,560.66) 290.48,560.66 295.41,565.59 296.54,565.59 314.75,583.8 314.75,662.34 343.55,691.13 343.55,756.16 327.18,772.53 327.18,985.05 411.38,1069.25 ; 411.35,1069.28 431.61,1089.54 v2@431.61,1127.76
  Bottom Layer w8: v2@434,1123.73 434,1110.05 447.9,1096.16 447.9,1080.65 U5.13@448.82,1079.72
  other v2: 433.07,1129.92
RESET: C136.1 R12.1 U7.1 | length 82.4
  Top Layer w8: U7.1@239.35,623.11 240.27,624.03 240.27,636.8 249.38,645.91 249.38,659.48 254.07,664.17 254.42,664.17 258.69,668.43 C136.1@258.69,669.22 ; C136.1@259.44,668.88 287.03,668.88 R12.1@287.36,668.54
SR1A2: R3.2 R5.1 U1.4 | length 96.6
  Top Layer w8: R3.2@849.41,391.02 849.41,395.03 860.73,406.35 872.01,406.35 v2@873.92,408.26
  Bottom Layer w8: R5.1@848.08,410.24 848.54,409.78 872.4,409.78 873.24,408.95 882.38,408.95 883.61,410.18 883.89,410.18 891.9,418.19 897.22,418.19 899.89,420.86 U1.4@899.89,426.18
  other v2: 873.92,407.03
SR1B2: R7.2 R37.1 U3.4 | length 99.3
  Top Layer w8: U3.4@974.41,426.18 974.41,420.86 986.75,408.51 1007.89,408.51 v2@1008.84,407.56 ; v2@1010.46,407.03 1014.55,402.95 1030.73,402.95 R7.2@1034.59,399.09
  Bottom Layer w8: v2@1008.41,407.37 1008.89,407.85 1033.64,407.85 R37.1@1034.45,408.66
  other v2: 1007.75,407.03
SR2A2: R42.2 R43.1 U6.4 | length 99.4
  Top Layer w8: U6.4@1765.27,426.81 1765.27,421.48 1777.81,408.95 v2@1795.9,408.95 ; v2(1797.27,407.03) 1799.98,407.03 1804.09,402.92 1820.1,402.92 R42.2@1824.2,398.83
  Bottom Layer w8: v2@1796.36,407.02 1797.51,408.16 1822.22,408.16 R43.1@1823.34,409.29
SR2B2: R40.2 R41.1 U4.4 | length 104.6
  Top Layer w8: R40.2@1630.01,389.62 R40.2@1631.75,389.62 ; R40.2@1634.48,390.93 1634.48,392.35 1647.25,405.12 1663.36,405.12 v2(1665.27,407.03)
  Bottom Layer w8: R41.1@1639.03,413.18 1656.42,413.18 1662.57,407.03 v2(1665.27,407.03) ; v2@1665.27,408.95 1677.93,408.95 1690.47,421.48 U4.4@1690.47,426.81
TEMP_P: C108.2 R31.1 RT1.1 U7.4 | length 264.6
  Top Layer w8: v2(169.62,668.84) 169.62,652.53 179.17,642.99 U7.4@179.17,622.93 ; R31.1@288.25,737.24 288.84,737.83 332.99,737.83 RT1.1@335.5,740.33 ; RT1.1@335.5,740.73 RT1.1@336.02,741.26
  Layer 4 w8: v2@168.39,669.76 169.05,669.76 202.82,703.53 237.18,703.53 269.77,736.12 v2(306.42,736.12)
TEMP_S: C109.2 R32.1 RT2.1 U7.6 | length 783
  Top Layer w8: v2(109.35,669.13) 109.55,669.13 119.8,658.88 119.8,656.53 129.4,646.92 129.98,646.92 140,636.9 140,623.85 U7.6@140.59,623.26 ; R32.1@392.99,388.64 394.37,387.26 437.38,387.26 v2(438.76,385.88) 490.27,385.88 521.81,354.34 RT2.1@525.99,354.34
  Layer 11 w8: v2@110.07,667.61 110.86,667.61 124.34,654.14 167.05,611.43 215.71,611.43 228.85,598.28 291.95,598.28 326.83,633.16 366.01,633.16 396.33,602.85 396.33,428.32 v2(438.76,385.88)
Vin: C1.2 C2.2 C3.2 C4.2 C5.2 C6.2 C7.2 C8.2 C9.2 C10.2 C123.1 C124.1 C125.1 C126.1 C127.1 C128.1 C137.2 C138.2 R21.2 U2.7 U5.7 Vin1.1 | length 345.6
  Layer 10 w8: v2(86.23,277.01) 87.78,277.01 101.86,262.94 116.16,262.94 127.21,251.89 205.93,251.89 239.93,217.89 239.93,148.17 277.15,110.94 277.15,66.67 Vin1.1@276.63,66.14
  other v2: 364.17,774.61 364.17,798.23 402.45,798.16 364.17,821.85 364.17,911.42 400.94,912.2 364.17,936.02 364.17,958.66
  other v3: 383.9,774.9 383.9,798.52 402.75,821.39 383.14,822.48 382.87,912.4 400.94,935.08 382.87,936.02 383.14,957.6
VINSNS: C104.2 R21.1 R24.2 U7.3 | length 517.4
  Top Layer w8: v2(35.03,314.21) 35.03,313.84 36.57,312.31 36.36,312.1 36.36,291.43 36.15,291.23 R21.1@36.15,269.57 ; v2(197.81,668.82) 197.81,632.17 199.47,630.51 U7.3@199.47,625.29
  Layer 4 w8: v2@35.3,314.51 35.45,314.66 35.45,335.51 55.29,355.35 65.06,355.35 88.39,378.68 88.39,545.37 196.02,653 v2@196.02,670
VOSNS2: C103.2 R20.1 R23.2 U7.2 | length 474.6
  Top Layer w8: R23.2@101.57,310.15 101.81,310.38 123.63,310.38 R20.1@123.97,310.72 ; U7.2@218.76,625.29 220.59,627.12 220.59,639.75 229.02,648.18 v2(229.02,668.84)
  Layer 4 w8: v2@113.49,313.84 113.49,336 131.81,354.33 131.81,389.31 130.57,390.54 130.57,455.09 134.22,458.74 134.22,523.29 163.49,552.56 167.2,552.56 229.02,614.37 229.02,666.45 v2@228.65,666.82
  other v2: 110.48,314.72
Vout: C14.2 C15.2 C16.2 C17.2 C18.2 C19.2 C20.2 C21.2 C22.2 C23.2 C24.2 C25.2 C26.2 C27.2 C28.2 C29.2 C30.2 C31.2 C32.2 C33.2 C34.2 C35.2 C36.2 C37.2 C51.2 C52.2 C53.2 C54.2 C55.2 C56.2 C57.2 C58.2 C59.2 C60.2 C61.2 C62.2 C66.2 C67.2 C68.2 C69.2 C70.2 C71.2 C72.2 C73.2 C74.2 C75.2 C76.2 C77.2 C115.1 C116.1 C117.1 C118.1 C119.1 C120.1 C121.1 C122.1 Q1.3 Q1.4 Q1.7 Q1.8 Q1.11 Q1.12 Q1.15 Q1.16 Q1.19 Q1.20 Q1.23 Q1.24 Q1.27 Q1.28 Q2.3 Q2.4 Q2.7 Q2.8 Q2.11 Q2.12 Q2.15 Q2.16 Q2.19 Q2.20 Q2.23 Q2.24 Q2.27 Q2.28 Q3.3 Q3.4 Q3.7 Q3.8 Q3.11 Q3.12 Q3.15 Q3.16 Q3.19 Q3.20 Q3.23 Q3.24 Q3.27 Q3.28 Q4.3 Q4.4 Q4.7 Q4.8 Q4.11 Q4.12 Q4.15 Q4.16 Q4.19 Q4.20 Q4.23 Q4.24 Q4.27 Q4.28 Q5.3 Q5.4 Q5.7 Q5.8 Q5.11 Q5.12 Q5.15 Q5.16 Q5.19 Q5.20 Q5.23 Q5.24 Q5.27 Q5.28 Q6.3 Q6.4 Q6.7 Q6.8 Q6.11 Q6.12 Q6.15 Q6.16 Q6.19 Q6.20 Q6.23 Q6.24 Q6.27 Q6.28 Q7.3 Q7.4 Q7.7 Q7.8 Q7.11 Q7.12 Q7.15 Q7.16 Q7.19 Q7.20 Q7.23 Q7.24 Q7.27 Q7.28 Q8.3 Q8.4 Q8.7 Q8.8 Q8.11 Q8.12 Q8.15 Q8.16 Q8.19 Q8.20 Q8.23 Q8.24 Q8.27 Q8.28 R2.2 R6.2 R20.2 R33.2 R35.2 TP1.1 TP2.1 TP3.1 TP4.1 TP5.1 TP6.1 Vout1.1 Vout2.1 Vout3.1 Vout4.1 Vout5.1 Vout6.1 | length 5516.1
  Top Layer w8: R20.2@124.38,285.73 R20.2@124.48,285.83 ; TP5.1@548.13,286.93 550.81,286.93 568.84,304.97 568.84,335.85 580.91,347.91 606.29,347.91 v2(606.77,348.4) ; Q1.27@606.89,322.06 Q1.28@606.89,374.43 Q1.28@606.89,376.03 ; Q1.23@638.38,322.06 Q1.24@638.38,374.69 ; Q1.19@669.88,322.06 v2@669.88,350.07 ; Q1.20@669.88,374.43 670.16,374.14 670.16,350.12 v2@670.21,350.07 ; Q1.15@701.37,322.06 Q1.16@701.37,374.43 ; Q1.11@732.87,322.06 Q1.12@732.87,374.43 ; Q1.7@764.37,322.06 Q1.8@764.37,374.43 ; Q1.3@795.66,334.47 v2@795.66,347.84 ; v2@795.86,348.76 Q1.4@795.86,374.43 ; v2(796.23,348.4) v2@796.78,347.84 ; R6.2@1031.11,367.18 1031.11,367.06 1036.68,361.49 1044.81,361.49 1056.65,349.65 v2@1085.64,349.65 ; Q3.4@1085.64,323.46 v2@1085.64,349.65 ; Q3.3@1085.64,375.82 v2@1085.64,349.65 ; v2(1085.84,349.65) v2@1085.64,349.65 ; Q3.8@1117.13,323.46 Q3.7@1117.13,375.82 ; Q3.12@1148.63,323.46 Q3.11@1148.63,375.82 ; Q3.16@1180.13,323.46 Q3.15@1180.13,375.82 ; Q3.20@1211.62,323.46 Q3.19@1211.62,375.82 ; Q3.24@1243.12,323.46 Q3.23@1243.12,375.82 ; Q3.28@1274.61,323.46 Q3.27@1274.61,375.82 ; v2(1275.3,349.65) 1275.71,349.24 1300.53,349.24 1331.4,318.37 TP3.1@1331.4,289.61 ; TP4.1@1331.4,411.23 1331.4,382.06 1363.09,350.36 1387,350.36 v2@1387.26,350.1 ; v2@1386.1,352.58 v2@1387.87,350.8 ; v2(1387.36,350) v2@1387.26,350.1 ; Q5.27@1388.31,323.78 1387.87,324.21 v2@1387.87,350.71 ; Q5.27@1388.31,333.56 Q5.28@1388.31,376.14 1387.87,375.71 v2@1387.87,350.8 ; Q5.23@1419.8,323.78 Q5.24@1419.8,376.14 ; Q5.19@1451.3,323.78 Q5.20@1451.3,376.14 ; Q5.15@1482.8,323.78 Q5.16@1482.8,376.14 ; Q5.11@1514.29,323.78 Q5.12@1514.29,376.14 ; Q5.7@1545.79,333.56 Q5.8@1545.79,376.14 ; Q5.3@1577.28,333.56 Q5.4@1577.28,376.14 ; R35.2@1823.11,366.54 1847.07,366.54 1862.94,350.67 1891.27,350.67 v2@1892.37,351.77 ; Q7.4@1892.76,324.89 v2@1892.76,350.59 ; v2@1892.76,351.77 Q7.3@1892.76,367.47 ; Q7.8@1924.05,336.55 1924.26,336.75 Q7.7@1924.26,377.25 ; Q7.12@1955.75,334.67 Q7.11@1955.75,377.25 ; Q7.16@1987.25,334.67 Q7.15@1987.25,377.25 ; Q7.20@2018.75,334.67 Q7.19@2018.75,377.25 ; Q7.24@2050.24,334.67 Q7.23@2050.24,377.25 ; Q7.28@2081.74,334.67 Q7.27@2081.74,377.25 ; v2(2081.76,350.59) 2081.85,350.67 2121.62,350.67 2154.86,383.9 TP2.1@2154.86,384.97 ; v2@1387.26,350.1 v2@1387.87,350.71 ; v2@1387.87,350.71 v2@1387.87,350.8
  Top Layer w50: C120.1@758.95,187.39 758.95,100.18 793.91,65.22 Vout4.1@793.91,61.81 ; Vout3.1@1105.65,61.81 1105.65,65.22 1143.09,102.66 C119.1@1143.09,187.39 ; C121.1@1535.72,187.39 1535.72,102.77 1573.27,65.22 Vout2.1@1573.27,61.81 ; Vout1.1@1885.02,61.81 1885.02,65.22 1919.87,100.07 C122.1@1919.87,187.39
  Layer 11 w8: v2@125.08,282.19 141.83,265.43 201.41,265.43 207.8,259.04 ; 207.64,258.89 239.93,226.61 239.93,182.39 285.91,136.41 357.59,136.41 cw(c357.59,93.11) 362.42,136.14 446.03,136.14 cw(c450.86,93.11) 450.86,136.41 513.46,136.41 cw(c513.46,93.11) 518.29,136.14 601.9,136.14 cw(c606.74,93.11) 606.74,136.41 669.33,136.41 cw(c669.33,93.11) 674.17,136.14 698.06,136.14 700.4,133.8 774.49,59.71 Vout4.1@788.1,59.71
  Layer 12 w8: Vout4.1@752.16,103.56 Vout4.1@793.91,61.81
  Bottom Layer w8: Q2.28@606.89,322.06 Q2.27@606.89,374.43 ; Q2.24@638.38,322.06 Q2.23@638.38,374.43 ; Q2.20@669.88,322.06 Q2.19@669.88,374.43 ; Q2.16@701.37,322.06 Q2.15@701.37,374.43 ; Q2.12@732.87,322.06 Q2.11@732.87,374.43 ; Q2.8@764.37,322.06 Q2.7@764.37,374.43 ; Q2.4@795.86,322.06 Q2.3@795.86,374.43 ; v2(796.23,348.4) 796.48,348.65 822.11,348.65 827.15,353.69 827.15,371.86 835.05,379.76 845.55,379.76 R2.2@849.31,383.52 ; Q4.3@1085.73,333.56 v2@1085.73,349.65 ; Q4.4@1085.73,376.14 v2@1085.73,349.65 ; v2@1087.62,351.03 1086.25,349.65 v2(1085.84,349.65) v2@1085.73,349.65 ; Q4.7@1117.23,323.78 Q4.8@1117.23,376.14 ; Q4.11@1148.72,323.78 Q4.12@1148.72,376.14 ; Q4.15@1180.22,323.78 Q4.16@1180.22,376.14 ; Q4.19@1211.72,323.78 Q4.20@1211.72,376.14 ; Q4.23@1243.21,323.78 Q4.24@1243.21,376.14 ; Q4.27@1274.71,323.78 Q4.28@1274.71,376.14 ; Q6.28@1388.25,324.14 Q6.27@1388.25,376.5 ; Q6.24@1419.74,324.14 Q6.23@1419.74,376.5 ; Q6.20@1451.24,324.14 Q6.19@1451.24,376.5 ; Q6.16@1482.74,324.14 Q6.15@1482.74,376.5 ; Q6.12@1514.23,324.14 Q6.11@1514.23,376.5 ; Q6.8@1545.79,323.78 Q6.7@1545.79,376.14 ; v2(1576.82,350) v2@1577.28,350 ; Q6.4@1577.28,323.78 v2@1577.28,350 ; Q6.3@1577.28,376.14 v2@1577.28,350 ; R33.2@1639.02,385.94 1635.6,382.52 1625.96,382.52 1612.71,369.27 1612.71,361.9 1600.81,350 v2@1577.28,350 ; Q8.3@1892.76,334.67 Q8.4@1892.76,377.25 ; Q8.7@1924.26,324.89 Q8.8@1924.26,377.25 ; Q8.11@1955.75,324.89 Q8.12@1955.75,377.25 ; Q8.15@1987.25,324.89 Q8.16@1987.25,377.25 ; Q8.19@2018.75,324.89 Q8.20@2018.75,377.25 ; Q8.23@2050.24,324.89 Q8.24@2050.24,377.25 ; Q8.27@2081.74,324.89 Q8.28@2081.74,377.25
  Bottom Layer w50: C118.1@748.49,187.39 748.49,110.64 793.91,65.22 Vout4.1@793.91,61.81 ; Vout3.1@1105.65,61.81 1136.87,93.03 C117.1@1136.87,187.39 ; C116.1@1528.25,187.39 1528.25,110.25 1573.27,65.22 Vout2.1@1573.27,61.81 ; Vout1.1@1885.02,61.81 1885.02,65.22 1924.62,104.82 C115.1@1924.62,187.39
  other v1: 850.37,495.61 868.57,495.61 886.78,495.61 904.99,495.61 923.2,495.61 941.41,495.61 959.61,495.61 977.82,495.61 996.03,495.61 1014.24,495.61 1664.58,496.06 1682.78,496.06 1700.99,496.06 1719.2,496.06 1737.41,496.06 1755.62,496.06 1773.82,496.06 1792.03,496.06 1810.24,496.06 1828.45,496.06
  other v2: 124.22,283.41 638.14,348.4 670.45,348.4 701.82,348.4 733.02,348.4 764.86,348.4 1117.21,349.65 1149.52,349.65 1180.89,349.65 1212.09,349.65 1243.93,349.65 1418.72,350 1451.04,350 1482.4,350 1513.61,350 1545.45,350 1892.31,350.59 1923.67,350.59 1955.99,350.59 1987.35,350.59 2018.56,350.59 2050.4,350.59
Vsw1: C39.2 C40.2 C41.2 C43.2 C44.2 C45.2 C46.2 C47.2 C49.2 C63.2 C64.2 C65.2 C78.2 C79.2 C81.2 C82.2 R25.1 TP7.1 TP9.1 U2.5 | length 2319
  Top Layer w8: U2.5@541.11,812.91 542.35,814.14 TP9.1@584.4,814.14 ; TP7.1@2093.86,798.81 2095.77,796.89 2143.71,796.89
  Layer 8 w8: v2(385.83,157.48) 388.53,157.48 394.26,163.2 2020.15,163.2 2156.5,299.55 2156.5,355.44 2237.66,436.6 2237.66,492.49 2213.47,516.69 2198.42,516.69 2191.46,523.65 v1@2191.46,523.77
  Bottom Layer w8: v2@384.24,158.3 385.33,159.39 391.1,159.39 423.64,191.93 R25.1@423.64,247.81
  other v1: 2171.6,518.99 2192.88,518.99 2171.6,604.34 2192.88,604.34 2171.6,689.69 2192.88,689.69 2171.6,775.05 2192.88,775.05 2171.6,860.4 2192.88,860.4 2171.6,945.76 2192.88,945.76 2171.6,1031.11 2192.88,1031.11 2171.6,1116.46 2192.88,1116.46
  other v2: 521.13,776.51 521.13,799.15 521.13,823.76 521.13,846.4
  other v3: 541.38,774.9 541.38,798.52 541.38,822.14 541.38,845.77
Vsw2: C39.1 C40.1 C41.1 C43.1 C44.1 C45.1 C46.1 C47.1 C49.1 C63.1 C64.1 C65.1 C78.1 C79.1 C81.1 C82.1 R17.1 TP8.1 U5.5 | length 2119.8
  Top Layer w8: 538.61,923.89 TP8.1@585.95,923.89
  Layer 8 w8: v2(386.33,184.33) 389.04,184.33 394.16,179.2 2013.53,179.2 2140.5,306.18 2140.5,362.07 2192.81,414.38 v1@2192.81,484.74
  Bottom Layer w8: R17.1@384.8,248.27 385.57,247.5 385.57,187.38 v2@387.1,185.85
  other v1: 2194.38,483.38 2215.66,483.38 1305.47,521.14 1366.6,521.14 1305.47,542.49 1366.6,542.49 1305.47,563.85 1366.6,563.85 2194.38,568.73 2215.66,568.73 1305.47,585.2 1366.6,585.2 2194.38,654.09 2215.66,654.09 1063.08,721 1586.13,728.07 1075.54,739.65 2194.38,739.44 2215.66,739.44 1577.15,747.42 1087.91,758.12 1569.55,766.76 1092.38,780.3 765.95,783.23 1564.71,788.87 762.45,806.7 1095.44,823.56 2194.38,824.79 2215.66,824.79 760.92,829.09 1558.23,829.64 1093.06,841.04 765.41,850.95 1562.61,851.64 1090.53,861.42 770.19,873.86 1567.1,873.12 1082.51,881.13 1573.81,892.13 780.68,896.33 2194.38,910.15 2215.66,910.15 793.96,917 810.88,938.42 2194.38,995.5 2215.66,995.5 2194.38,1080.86 2215.66,1080.86 1285.03,1093.56 1305.96,1093.56 1367.09,1093.56 1389.21,1093.38 1284.62,1115.8 1305.96,1115.8 1367.09,1115.8 1389.62,1115.62
  other v2: 521.13,890.75 521.13,913.38 521.13,937.99 521.13,960.63
  other v3: 540.35,888.78 540.35,912.4 540.35,936.02 540.35,959.65
X1: C85.1 R13.1 U7.22 | length 123.2
  Top Layer w8: R13.1@157.11,351.29 C85.1@188.98,351.29 ; C85.1@192.42,349.17 194.25,350.99 194.25,375.62 193.32,376.55 193.32,397.18 199.98,403.84 U7.22@199.98,434.14 199.98,436.16 U7.22@199.67,436.47
pads on no net: J1.5 J1.7 Q1. Q2. Q3. Q4. Q5. Q6. Q7. Q8. RT1.1S RT1.2S RT2.1S RT2.2S U1.7@937.3,373.03 U2.1 U2.2 U2.3 U2.4 U2.8 U2.9 U2.16 U3.7@937.01,373.03 U4.7@1727.87,373.66 U5.1 U5.2 U5.3 U5.4 U5.8 U5.9 U5.16 U6.7@1727.87,373.66 U7.7 U7.9 U7.12 U7.14 U7.32 U8.2 U8.5 U8.7@354.9,273.59 U8.7@354.9,309.02

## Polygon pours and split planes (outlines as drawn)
3_3V_D on Layer 2 "LAYER_2_3_3V_D_P1355" (solid, pour order 1355): 18.39,765.74 307.08,765.74 307.08,641.01 307.08,240.65 17.11,240.65
Vsw2 on Layer 2 "LAYER_2_VSW2_P1378" (solid, remove dead copper, pour order 1378): 560.6,976.49 514.62,976.49 514.62,873.03 560.21,873.03
Vin on Layer 2 "LAYER_2_VIN_P1347" (solid, remove dead copper, pour order 1347): 258.75,-0.36 258.75,190.9 285.93,218.07 285.93,970.38 410.25,970.38 410.25,-0.36
Vsw2 on Layer 2 "LAYER_2_VSW2_P1360" (solid, pour order 1360): 1019,702.35 1102.45,702.35 1452.37,1052.26 1452.37,1157.48 1336.59,1157.48 1336.59,1041.7 1091.16,796.27 1019,796.27
Vsw2 on Layer 2 "LAYER_2_VSW2_P1359" (solid, pour order 1359): 1623.34,913.48 1544.79,913.48 1224.94,593.63 1224.94,464.14 1337.82,464.14 1337.82,615.42 1537.09,814.69 1623.34,814.69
